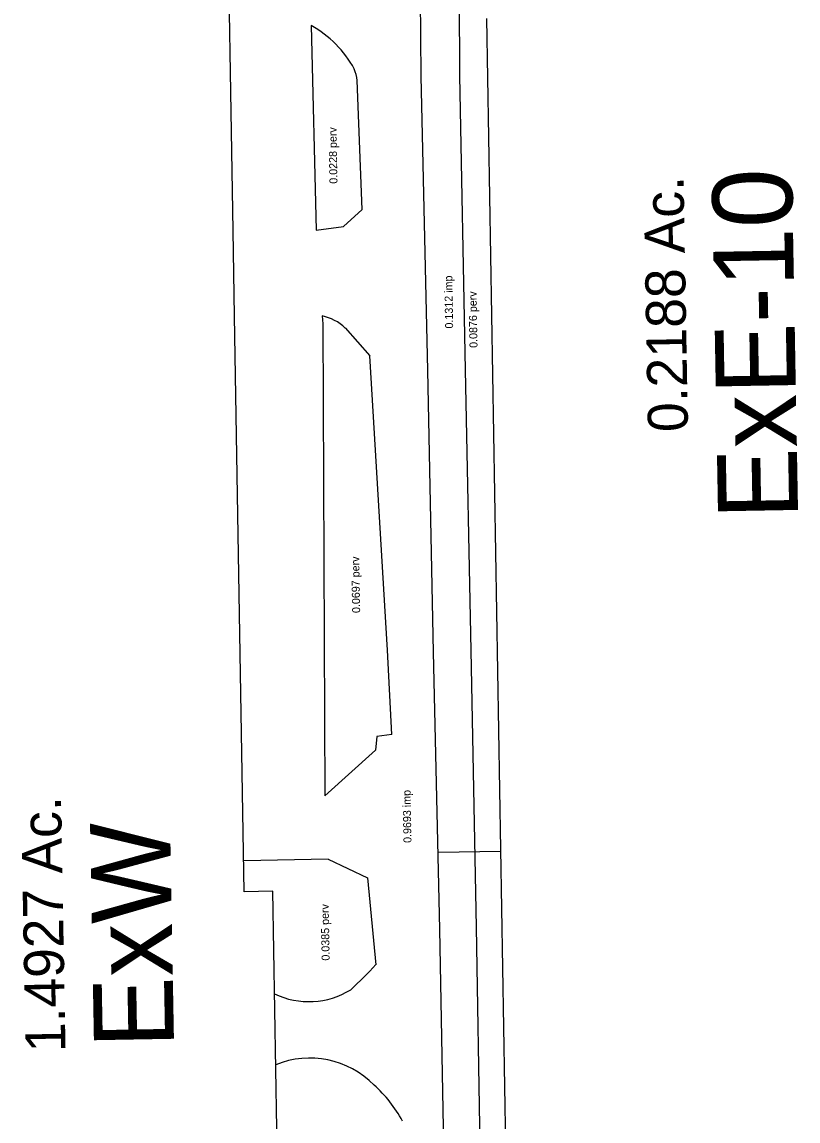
# Model space of a CAD drawing. Extents: x 925564 to 926134, y 853260 to 858402.
# Drawn here: x 925639.1 to 925910.6, y 856794.5 to 857179 of the extents above; entities that cross this region are included whole.
import ezdxf

# ---------------------------------------------------------------- set-up
doc = ezdxf.new("R2010")
doc.units = 0
for name, color, linetype in [('DrainDivides01', 7, 'Continuous'), ('PavtMisc_ep', 7, 'Continuous'), ('TextLabel', 7, 'Continuous')]:
    doc.layers.add(name, color=color, linetype=linetype)

msp = doc.modelspace()

# ---------------------------------------------------------------- linework, layer by layer
at = {"layer": 'DrainDivides01'}
for p, q in [((925778.72, 857160.03), (925777.87, 857269.9)), ((925809.63, 856710.62), (925801.78, 857180.29)), ((925781.12, 857057.06), (925778.72, 857160.03)), ((925783.1, 856958.55), (925781.12, 857057.06)), ((925785.29, 856861.65), (925783.1, 856958.55)), ((925784.69, 856888.53), (925806.65, 856888.89)), ((925787.22, 856762.22), (925785.29, 856861.65))]:
    msp.add_line(p, q, dxfattribs=at)
msp.add_lwpolyline([(925724.71, 856410.17), (925734.71, 856410.34), (925730.14, 856679.29), (925729.65, 856708.82), (925726.87, 856874.9), (925716.87, 856874.74), (925713.51, 857076.08), (925713.01, 857106.07), (925708.61, 857369.25)], dxfattribs=at)
at = {"layer": 'PavtMisc_ep'}
for p, q in [((925792.31, 857160.22), (925791.96, 857270.25)), ((925740.35, 857177.75), (925742.09, 857106.19)), ((925794.28, 857057.3), (925792.31, 857160.22)), ((925758.12, 857113.47), (925756.33, 857158.56)), ((925751.64, 857107.42), (925758.12, 857113.47)), ((925742.09, 857106.19), (925751.64, 857107.42)), ((925752.22, 857071.96), (925760.77, 857062.22)), ((925767.01, 856959.28), (925760.77, 857062.22)), ((925796.27, 856959.12), (925794.28, 857057.3)), ((925768.54, 856929.73), (925767.01, 856959.28)), ((925798.18, 856862.33), (925796.27, 856959.12)), ((925763.29, 856929.03), (925762.75, 856924.22)), ((925768.54, 856929.73), (925763.29, 856929.03)), ((925762.75, 856924.22), (925745.11, 856908.3)), ((925746.25, 856886.11), (925716.69, 856885.6)), ((925746.25, 856886.11), (925760, 856879.61)), ((925760, 856879.61), (925762.97, 856849.22)), ((925799.77, 856761.9), (925798.18, 856862.33))]:
    msp.add_line(p, q, dxfattribs=at)
msp.add_lwpolyline([(925744.18, 857076.19), (925744.37, 857073.38), (925745.11, 856908.3)], dxfattribs=at)
for centre, major_axis, ratio, start_param, end_param in [((925721.42, 857143.96), (-23.44, -30.84), 0.998282, 2.721507, 3.28139), ((925743.21, 857157.53), (0.78, -13.23), 0.993494, 1.590301, 1.90257), ((925740.83, 857060.1), (13.45, 9.46), 0.998353, 0.192794, 0.753381), ((925661.77, 856943.63), (-54.25, -128.34), 0.992365, 1.132968, 1.222475), ((925739.46, 856864.07), (25.73, -10.55), 0.998683, 4.655059, 5.656305), ((925739.78, 856785.01), (-27.37, -15.66), 0.999067, 3.398251, 4.580078), ((925732.35, 856773.28), (-33.93, -29.82), 0.999208, 2.910109, 3.266922)]:
    msp.add_ellipse(centre, major_axis=major_axis, ratio=ratio, start_param=start_param, end_param=end_param, dxfattribs=at)

# ---------------------------------------------------------------- texts
at = {"layer": 'TextLabel'}
for s, height, p in [('0.0228 perv', 2.8, (925749.5, 857122.46)), ('ExE-10', 28, (925910.65, 857005.25)), ('0.2188 Ac.', 14, (925872.13, 857035.68)), ('0.1312 imp', 2.8, (925789.97, 857071.8)), ('0.0876 perv', 2.8, (925798.49, 857065.03)), ('0.0697 perv', 2.8, (925757.44, 856972.27)), ('0.9693 imp', 2.8, (925775.39, 856891.84)), ('1.4927 Ac.', 14, (925654.39, 856818.69)), ('ExW', 28, (925692.35, 856820.22)), ('0.0385 perv', 2.8, (925746.77, 856850.66))]:
    msp.add_text(s, height=height, rotation=91.0261, dxfattribs=at).set_placement(p)

doc.saveas('drawing.dxf')
